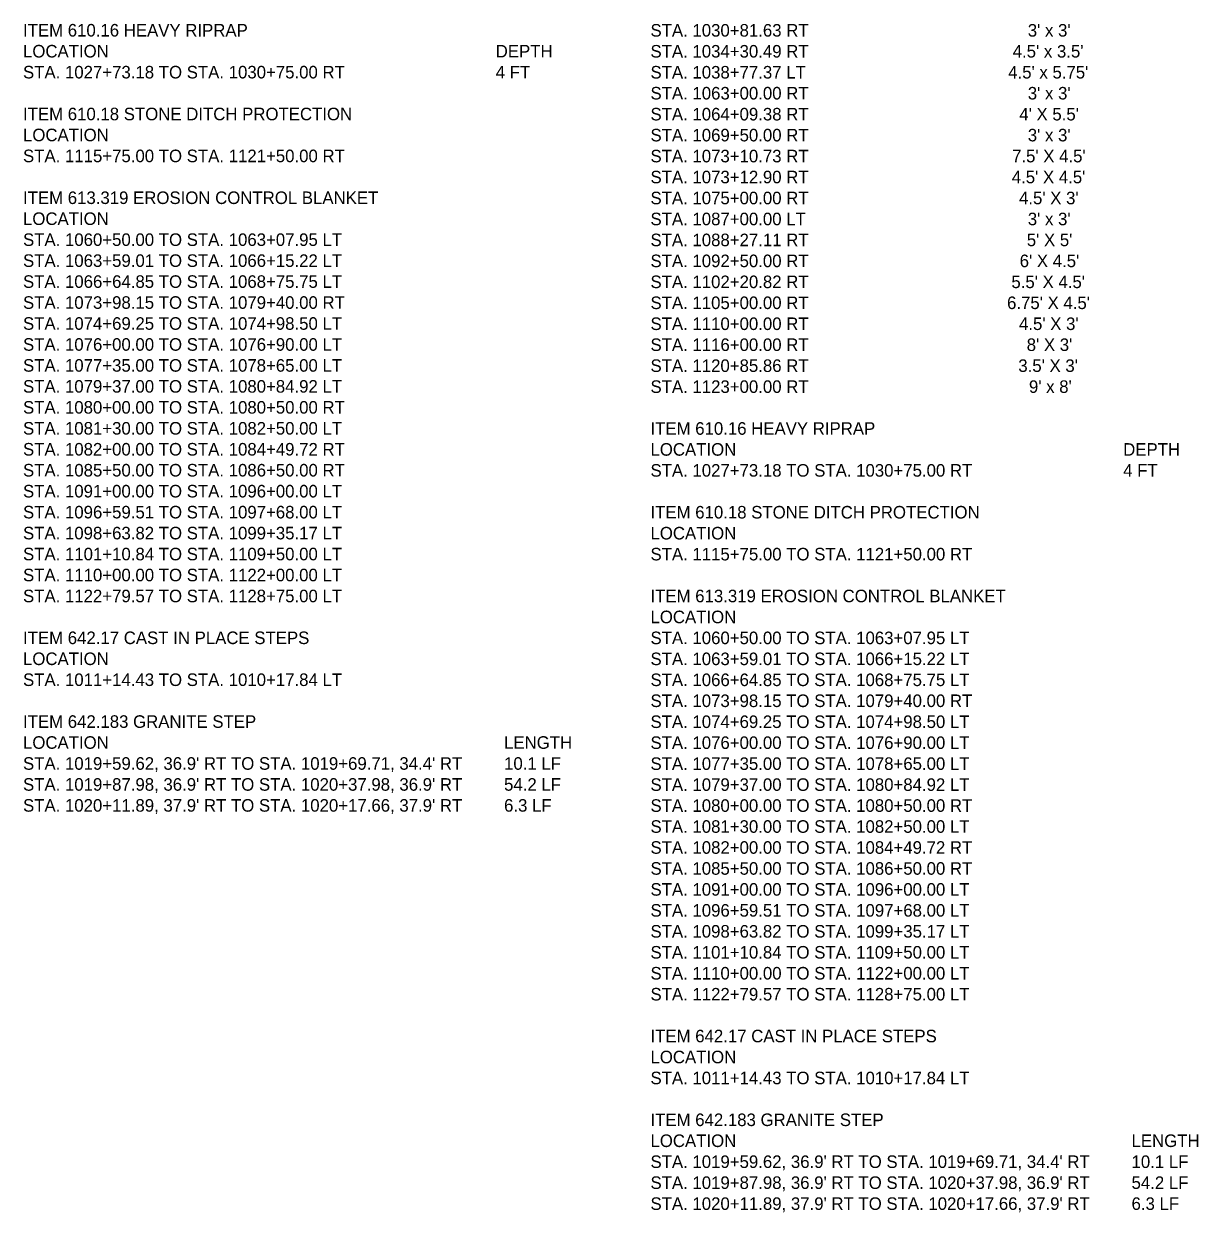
# Model space of a CAD drawing. Extents: x -831 to 3331, y -1004 to 250.
# Drawn here: x -306.6 to -25.8, y -1004.3 to -720.2 of the extents above; entities that cross this region are included whole.
import ezdxf

# ---------------------------------------------------------------- set-up
doc = ezdxf.new("R2010")
doc.units = 0
doc.layers.add('Default', color=7, linetype='Continuous')

msp = doc.modelspace()

# ---------------------------------------------------------------- texts
at = {"layer": 'Default'}
for s, p in [('ITEM 610.16 HEAVY RIPRAP', (-306.76, -723.28)), ('STA. 1030+81.63 RT', (-156.76, -723.3)), ("3' x 3'", (-66.56, -723.3)), ('LOCATION', (-306.76, -728.29)), ('DEPTH', (-193.76, -728.29)), ('STA. 1034+30.49 RT', (-156.76, -728.31)), ("4.5' x 3.5'", (-70.17, -728.31)), ('STA. 1027+73.18 TO STA. 1030+75.00 RT', (-306.76, -733.3)), ('4 FT', (-193.76, -733.3)), ('STA. 1038+77.37 LT', (-156.76, -733.32)), ("4.5' x 5.75'", (-71.24, -733.32)), ('STA. 1063+00.00 RT', (-156.76, -738.33)), ("3' x 3'", (-66.56, -738.33)), ('ITEM 610.18 STONE DITCH PROTECTION', (-306.76, -743.3)), ('STA. 1064+09.38 RT', (-156.76, -743.34)), ("4' X 5.5'", (-68.59, -743.34)), ('LOCATION', (-306.76, -748.31)), ('STA. 1069+50.00 RT', (-156.76, -748.35)), ("3' x 3'", (-66.56, -748.35)), ('STA. 1115+75.00 TO STA. 1121+50.00 RT', (-306.76, -753.32)), ('STA. 1073+10.73 RT', (-156.76, -753.36)), ("7.5' X 4.5'", (-70.32, -753.36)), ('STA. 1073+12.90 RT', (-156.76, -758.37)), ("4.5' X 4.5'", (-70.39, -758.37)), ('ITEM 613.319 EROSION CONTROL BLANKET', (-306.76, -763.32)), ('STA. 1075+00.00 RT', (-156.76, -763.38)), ("4.5' X 3'", (-68.66, -763.38)), ('LOCATION', (-306.76, -768.33)), ('STA. 1087+00.00 LT', (-156.76, -768.39)), ("3' x 3'", (-66.56, -768.39)), ('STA. 1060+50.00 TO STA. 1063+07.95 LT', (-306.76, -773.34)), ('STA. 1088+27.11 RT', (-156.76, -773.4)), ("5' X 5'", (-66.8, -773.4)), ('STA. 1063+59.01 TO STA. 1066+15.22 LT', (-306.76, -778.35)), ('STA. 1092+50.00 RT', (-156.76, -778.41)), ("6' X 4.5'", (-68.5, -778.41)), ('STA. 1066+64.85 TO STA. 1068+75.75 LT', (-306.76, -783.36)), ('STA. 1102+20.82 RT', (-156.76, -783.42)), ("5.5' X 4.5'", (-70.48, -783.42)), ('STA. 1073+98.15 TO STA. 1079+40.00 RT', (-306.76, -788.37)), ('STA. 1105+00.00 RT', (-156.76, -788.43)), ("6.75' X 4.5'", (-71.52, -788.43)), ('STA. 1074+69.25 TO STA. 1074+98.50 LT', (-306.76, -793.38)), ('STA. 1110+00.00 RT', (-156.76, -793.44)), ("4.5' X 3'", (-68.66, -793.44)), ('STA. 1076+00.00 TO STA. 1076+90.00 LT', (-306.76, -798.39)), ('STA. 1116+00.00 RT', (-156.76, -798.45)), ("8' X 3'", (-66.82, -798.45)), ('STA. 1077+35.00 TO STA. 1078+65.00 LT', (-306.76, -803.4)), ('STA. 1120+85.86 RT', (-156.76, -803.46)), ("3.5' X 3'", (-68.83, -803.46)), ('STA. 1079+37.00 TO STA. 1080+84.92 LT', (-306.76, -808.41)), ('STA. 1123+00.00 RT', (-156.76, -808.47)), ("9' x 8'", (-66.28, -808.47)), ('STA. 1080+00.00 TO STA. 1080+50.00 RT', (-306.76, -813.42)), ('STA. 1081+30.00 TO STA. 1082+50.00 LT', (-306.76, -818.43)), ('ITEM 610.16 HEAVY RIPRAP', (-156.76, -818.47)), ('STA. 1082+00.00 TO STA. 1084+49.72 RT', (-306.76, -823.44)), ('LOCATION', (-156.76, -823.48)), ('DEPTH', (-43.76, -823.48)), ('STA. 1085+50.00 TO STA. 1086+50.00 RT', (-306.76, -828.45)), ('STA. 1027+73.18 TO STA. 1030+75.00 RT', (-156.76, -828.49)), ('4 FT', (-43.76, -828.49)), ('STA. 1091+00.00 TO STA. 1096+00.00 LT', (-306.76, -833.46)), ('STA. 1096+59.51 TO STA. 1097+68.00 LT', (-306.76, -838.47)), ('ITEM 610.18 STONE DITCH PROTECTION', (-156.76, -838.49)), ('STA. 1098+63.82 TO STA. 1099+35.17 LT', (-306.76, -843.48)), ('LOCATION', (-156.76, -843.5)), ('STA. 1101+10.84 TO STA. 1109+50.00 LT', (-306.76, -848.49)), ('STA. 1115+75.00 TO STA. 1121+50.00 RT', (-156.76, -848.51)), ('STA. 1110+00.00 TO STA. 1122+00.00 LT', (-306.76, -853.5)), ('STA. 1122+79.57 TO STA. 1128+75.00 LT', (-306.76, -858.51)), ('ITEM 613.319 EROSION CONTROL BLANKET', (-156.76, -858.51)), ('LOCATION', (-156.76, -863.52)), ('ITEM 642.17 CAST IN PLACE STEPS', (-306.76, -868.51)), ('STA. 1060+50.00 TO STA. 1063+07.95 LT', (-156.76, -868.53)), ('LOCATION', (-306.76, -873.52)), ('STA. 1063+59.01 TO STA. 1066+15.22 LT', (-156.76, -873.54)), ('STA. 1011+14.43 TO STA. 1010+17.84 LT', (-306.76, -878.53)), ('STA. 1066+64.85 TO STA. 1068+75.75 LT', (-156.76, -878.55)), ('STA. 1073+98.15 TO STA. 1079+40.00 RT', (-156.76, -883.56)), ('ITEM 642.183 GRANITE STEP', (-306.76, -888.53)), ('STA. 1074+69.25 TO STA. 1074+98.50 LT', (-156.76, -888.57)), ('LOCATION', (-306.76, -893.54)), ('LENGTH', (-191.76, -893.54)), ('STA. 1076+00.00 TO STA. 1076+90.00 LT', (-156.76, -893.58)), ("STA. 1019+59.62, 36.9' RT TO STA. 1019+69.71, 34.4' RT", (-306.76, -898.55)), ('10.1 LF', (-191.76, -898.55)), ('STA. 1077+35.00 TO STA. 1078+65.00 LT', (-156.76, -898.59)), ("STA. 1019+87.98, 36.9' RT TO STA. 1020+37.98, 36.9' RT", (-306.76, -903.56)), ('54.2 LF', (-191.76, -903.56)), ('STA. 1079+37.00 TO STA. 1080+84.92 LT', (-156.76, -903.6)), ("STA. 1020+11.89, 37.9' RT TO STA. 1020+17.66, 37.9' RT", (-306.76, -908.57)), ('6.3 LF', (-191.76, -908.57)), ('STA. 1080+00.00 TO STA. 1080+50.00 RT', (-156.76, -908.61)), ('STA. 1081+30.00 TO STA. 1082+50.00 LT', (-156.76, -913.62)), ('STA. 1082+00.00 TO STA. 1084+49.72 RT', (-156.76, -918.63)), ('STA. 1085+50.00 TO STA. 1086+50.00 RT', (-156.76, -923.64)), ('STA. 1091+00.00 TO STA. 1096+00.00 LT', (-156.76, -928.65)), ('STA. 1096+59.51 TO STA. 1097+68.00 LT', (-156.76, -933.66)), ('STA. 1098+63.82 TO STA. 1099+35.17 LT', (-156.76, -938.67)), ('STA. 1101+10.84 TO STA. 1109+50.00 LT', (-156.76, -943.68)), ('STA. 1110+00.00 TO STA. 1122+00.00 LT', (-156.76, -948.69)), ('STA. 1122+79.57 TO STA. 1128+75.00 LT', (-156.76, -953.7)), ('ITEM 642.17 CAST IN PLACE STEPS', (-156.76, -963.7)), ('LOCATION', (-156.76, -968.71)), ('STA. 1011+14.43 TO STA. 1010+17.84 LT', (-156.76, -973.72)), ('ITEM 642.183 GRANITE STEP', (-156.76, -983.72)), ('LOCATION', (-156.76, -988.73)), ('LENGTH', (-41.76, -988.73)), ("STA. 1019+59.62, 36.9' RT TO STA. 1019+69.71, 34.4' RT", (-156.76, -993.74)), ('10.1 LF', (-41.76, -993.74)), ("STA. 1019+87.98, 36.9' RT TO STA. 1020+37.98, 36.9' RT", (-156.76, -998.75)), ('54.2 LF', (-41.76, -998.75)), ("STA. 1020+11.89, 37.9' RT TO STA. 1020+17.66, 37.9' RT", (-156.76, -1003.76)), ('6.3 LF', (-41.76, -1003.76))]:
    msp.add_text(s, height=3, dxfattribs=at).set_placement(p)

doc.saveas('drawing.dxf')
